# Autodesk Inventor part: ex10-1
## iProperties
Created: 2006-03
Part Number: ex10-1
Material: Aluminum-6061
Document SubType Name: Sheet Metal
Designer: Elise Moss
Author: Elise Moss
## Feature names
1. Hole1
2. Plate1
3. Plate2
4. Bend1
5. Plate3
6. Bend2
7. Plate4
8. Bend3
9. Plate5
10. Bend4
11. Plate6
12. Bend5
13. Plate7
14. Bend6
